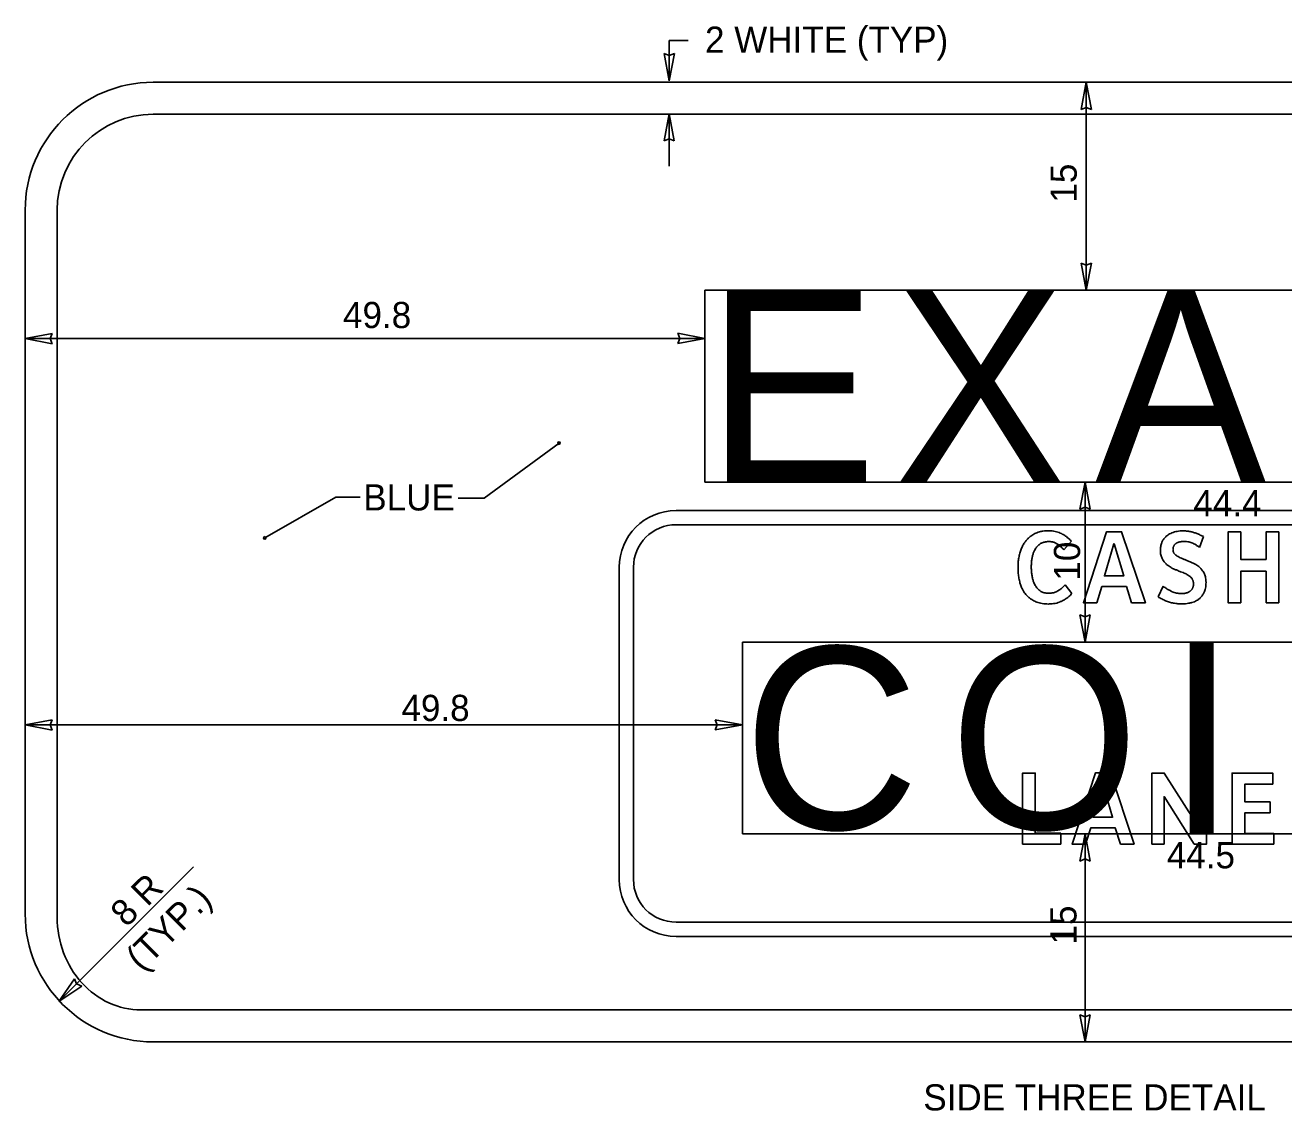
# Model space of a CAD drawing. Extents: x 319706 to 320346, y 1621790 to 1622121.
# Drawn here: x 319720.4 to 319787.7, y 1622061.2 to 1622119.2 of the extents above; entities that cross this region are included whole.
import ezdxf

# ---------------------------------------------------------------- set-up
doc = ezdxf.new("R2010")
doc.units = 0
for name, color, linetype in [('1', 7, 'Continuous'), ('52', 7, 'Continuous'), ('GSOutline', 7, 'Continuous'), ('SignPanel', 7, 'Continuous'), ('SOILS_SP83_SHP', 7, 'Continuous')]:
    doc.layers.add(name, color=color, linetype=linetype)

msp = doc.modelspace()

# ---------------------------------------------------------------- linework, layer by layer
at = {"layer": '1'}
for p, q in [((319754.849, 1622116.226), (319754.849, 1622118.372)), ((319754.849, 1622118.372), (319755.859, 1622118.372)), ((319777.142, 1622116.142), (319777.142, 1622105.027)), ((319754.849, 1622111.65), (319754.849, 1622114.46)), ((319720.417, 1622102.447), (319756.748, 1622102.447)), ((319744.954, 1622093.91), (319748.959, 1622096.856)), ((319777.075, 1622094.767), (319777.075, 1622086.218)), ((319737.031, 1622093.965), (319733.225, 1622091.783)), ((319738.317, 1622093.965), (319737.031, 1622093.965)), ((319743.57, 1622093.91), (319744.954, 1622093.91)), ((319720.417, 1622081.786), (319758.755, 1622081.786)), ((319722.216, 1622066.995), (319729.415, 1622074.193))]:
    msp.add_line(p, q, dxfattribs=at)
for centre in [(319748.958, 1622096.855), (319733.224, 1622091.782)]:
    msp.add_ellipse(centre, major_axis=(0, 0.0707), ratio=0.906668, dxfattribs=at)
at = {"layer": '52'}
for p, q in [((319754.849, 1622117.566), (319754.579, 1622117.676)), ((319754.579, 1622117.676), (319754.849, 1622116.226)), ((319754.849, 1622116.226), (319755.129, 1622117.676)), ((319755.129, 1622117.676), (319754.849, 1622117.566)), ((319777.142, 1622116.142), (319776.862, 1622114.692)), ((319777.412, 1622114.692), (319777.142, 1622116.142)), ((319776.862, 1622114.692), (319777.142, 1622114.802)), ((319777.142, 1622114.802), (319777.412, 1622114.692)), ((319754.849, 1622114.46), (319754.569, 1622113.01)), ((319755.119, 1622113.01), (319754.849, 1622114.46)), ((319754.569, 1622113.01), (319754.849, 1622113.12)), ((319754.849, 1622113.12), (319755.119, 1622113.01)), ((319777.142, 1622106.367), (319776.872, 1622106.477)), ((319776.872, 1622106.477), (319777.142, 1622105.027)), ((319777.142, 1622105.027), (319777.422, 1622106.477)), ((319777.422, 1622106.477), (319777.142, 1622106.367)), ((319721.867, 1622102.717), (319720.417, 1622102.447)), ((319721.757, 1622102.447), (319721.867, 1622102.717)), ((319756.748, 1622102.447), (319755.298, 1622102.727)), ((319755.298, 1622102.727), (319755.408, 1622102.447)), ((319720.417, 1622102.447), (319721.867, 1622102.167)), ((319721.867, 1622102.167), (319721.757, 1622102.447)), ((319755.408, 1622102.447), (319755.298, 1622102.177)), ((319755.298, 1622102.177), (319756.748, 1622102.447)), ((319777.075, 1622094.767), (319776.795, 1622093.317)), ((319777.345, 1622093.317), (319777.075, 1622094.767)), ((319776.795, 1622093.317), (319777.075, 1622093.427)), ((319777.075, 1622093.427), (319777.345, 1622093.317)), ((319777.075, 1622087.558), (319776.805, 1622087.668)), ((319776.805, 1622087.668), (319777.075, 1622086.218)), ((319777.075, 1622086.218), (319777.355, 1622087.668)), ((319777.355, 1622087.668), (319777.075, 1622087.558)), ((319721.867, 1622082.056), (319720.417, 1622081.786)), ((319720.417, 1622081.786), (319721.867, 1622081.506)), ((319721.757, 1622081.786), (319721.867, 1622082.056)), ((319721.867, 1622081.506), (319721.757, 1622081.786)), ((319758.755, 1622081.786), (319757.305, 1622082.066)), ((319757.305, 1622082.066), (319757.415, 1622081.786)), ((319757.415, 1622081.786), (319757.305, 1622081.516)), ((319757.305, 1622081.516), (319758.755, 1622081.786)), ((319777.075, 1622075.958), (319776.795, 1622074.508)), ((319777.345, 1622074.508), (319777.075, 1622075.958)), ((319776.795, 1622074.508), (319777.075, 1622074.618)), ((319777.075, 1622074.618), (319777.345, 1622074.508)), ((319723.05, 1622068.212), (319722.216, 1622066.995)), ((319723.163, 1622067.943), (319723.05, 1622068.212)), ((319722.216, 1622066.995), (319723.439, 1622067.823)), ((319723.439, 1622067.823), (319723.163, 1622067.943)), ((319777.075, 1622066.182), (319776.805, 1622066.292)), ((319776.805, 1622066.292), (319777.075, 1622064.842)), ((319777.075, 1622064.842), (319777.355, 1622066.292)), ((319777.355, 1622066.292), (319777.075, 1622066.182))]:
    msp.add_line(p, q, dxfattribs=at)
at = {"layer": 'GSOutline'}
for p, q in [((319803.779, 1622093.246), (319755.212, 1622093.246)), ((319803.779, 1622092.488), (319755.212, 1622092.488)), ((319752.176, 1622090.211), (319752.176, 1622073.516)), ((319752.935, 1622090.211), (319752.935, 1622073.516)), ((319755.212, 1622071.24), (319803.779, 1622071.24)), ((319755.212, 1622070.481), (319803.779, 1622070.481))]:
    msp.add_line(p, q, dxfattribs=at)
for points in [[(319779.566, 1622088.314), (319779.289, 1622089.181), (319777.977, 1622089.181), (319777.7, 1622088.314), (319776.988, 1622088.314), (319778.231, 1622092.117), (319779.031, 1622092.117), (319780.302, 1622088.314), (319779.566, 1622088.314)], [(319783.404, 1622091.852), (319783.203, 1622091.279)], [(319786.753, 1622088.314), (319786.753, 1622090.001), (319785.402, 1622090.001), (319785.402, 1622088.314), (319784.72, 1622088.314), (319784.72, 1622092.108), (319785.402, 1622092.108), (319785.402, 1622090.637), (319786.753, 1622090.637), (319786.753, 1622092.108), (319787.435, 1622092.108), (319787.435, 1622088.314), (319786.753, 1622088.314)], [(319776.351, 1622091.61), (319775.945, 1622091.14)], [(319778.641, 1622091.472), (319778.622, 1622091.473), (319778.114, 1622089.752), (319779.149, 1622089.752), (319778.641, 1622091.472)], [(319776.014, 1622089.277), (319776.378, 1622088.803)], [(319780.987, 1622088.63), (319781.245, 1622089.199)], [(319773.734, 1622075.413), (319773.734, 1622079.208), (319774.416, 1622079.208), (319774.416, 1622075.994), (319775.777, 1622075.994), (319775.777, 1622075.413), (319773.734, 1622075.413)], [(319778.965, 1622075.413), (319778.689, 1622076.28), (319777.377, 1622076.28), (319777.1, 1622075.413), (319776.387, 1622075.413), (319777.631, 1622079.217), (319778.431, 1622079.217), (319779.701, 1622075.413), (319778.965, 1622075.413)], [(319782.915, 1622075.413), (319781.31, 1622077.955), (319781.301, 1622077.955), (319781.301, 1622075.413), (319780.651, 1622075.413), (319780.651, 1622079.208), (319781.31, 1622079.208), (319782.906, 1622076.692), (319782.914, 1622076.692), (319782.915, 1622079.208), (319783.569, 1622079.208), (319783.569, 1622075.413), (319782.915, 1622075.413)], [(319784.939, 1622075.413), (319784.939, 1622079.208), (319787.11, 1622079.208), (319787.11, 1622078.627), (319785.621, 1622078.627), (319785.621, 1622077.672), (319786.967, 1622077.672), (319786.967, 1622077.087), (319785.621, 1622077.087), (319785.621, 1622075.98), (319787.168, 1622075.98), (319787.168, 1622075.413), (319784.939, 1622075.413)], [(319778.04, 1622078.571), (319778.021, 1622078.572), (319777.513, 1622076.852), (319778.548, 1622076.852), (319778.04, 1622078.571)]]:
    msp.add_lwpolyline(points, dxfattribs=at)
for centre, radius, start, end in [((319755.212, 1622090.211), 3.035, 90, 180), ((319755.212, 1622090.211), 2.277, 90, 180), ((319755.212, 1622073.516), 3.035, 180, 270), ((319755.212, 1622073.516), 2.277, 180, 270)]:
    msp.add_arc(centre, radius, start, end, dxfattribs=at)
for points in [[(319773.492, 1622090.218), (319773.493, 1622090.283), (319773.497, 1622090.474), (319773.53, 1622090.724), (319773.586, 1622090.965), (319773.657, 1622091.19), (319773.756, 1622091.399), (319773.867, 1622091.564), (319773.952, 1622091.673), (319774.047, 1622091.773), (319774.174, 1622091.88), (319774.291, 1622091.957), (319774.391, 1622092.012), (319774.496, 1622092.061), (319774.639, 1622092.111), (319774.824, 1622092.15), (319774.987, 1622092.166), (319775.087, 1622092.168), (319775.122, 1622092.168)], [(319775.122, 1622092.168), (319775.153, 1622092.168), (319775.242, 1622092.166), (319775.387, 1622092.152), (319775.554, 1622092.118), (319775.685, 1622092.074), (319775.81, 1622092.019), (319775.984, 1622091.923), (319776.175, 1622091.781), (319776.305, 1622091.655), (319776.351, 1622091.61)], [(319781.104, 1622091.13), (319781.105, 1622091.153), (319781.105, 1622091.218), (319781.116, 1622091.322), (319781.141, 1622091.439), (319781.172, 1622091.53), (319781.204, 1622091.597), (319781.239, 1622091.66), (319781.288, 1622091.734), (319781.356, 1622091.814), (319781.419, 1622091.873), (319781.488, 1622091.927), (319781.591, 1622091.996), (319781.721, 1622092.058), (319781.86, 1622092.102), (319782.005, 1622092.136), (319782.155, 1622092.156), (319782.269, 1622092.158), (319782.307, 1622092.159)], [(319782.307, 1622092.159), (319782.358, 1622092.158), (319782.505, 1622092.155), (319782.698, 1622092.127), (319782.882, 1622092.079), (319783.061, 1622092.018), (319783.236, 1622091.943), (319783.361, 1622091.875), (319783.404, 1622091.852)], [(319775.138, 1622091.587), (319775.119, 1622091.587), (319775.063, 1622091.586), (319774.972, 1622091.576), (319774.869, 1622091.553), (319774.789, 1622091.524), (319774.729, 1622091.495), (319774.672, 1622091.462), (319774.604, 1622091.414), (319774.531, 1622091.346), (319774.476, 1622091.282), (319774.436, 1622091.225), (319774.367, 1622091.114), (319774.306, 1622090.969), (319774.259, 1622090.792), (319774.224, 1622090.612), (319774.205, 1622090.419), (319774.203, 1622090.27), (319774.202, 1622090.218)], [(319775.945, 1622091.14), (319775.914, 1622091.175), (319775.855, 1622091.241), (319775.777, 1622091.318), (319775.7, 1622091.386), (319775.637, 1622091.433), (319775.572, 1622091.474), (319775.507, 1622091.509), (319775.439, 1622091.538), (319775.369, 1622091.559), (319775.295, 1622091.576), (319775.218, 1622091.586), (319775.158, 1622091.587), (319775.138, 1622091.587)], [(319782.183, 1622089.977), (319782.12, 1622090.002), (319781.993, 1622090.052), (319781.836, 1622090.119), (319781.681, 1622090.193), (319781.564, 1622090.265), (319781.47, 1622090.337), (319781.406, 1622090.392), (319781.335, 1622090.465), (319781.263, 1622090.56), (319781.21, 1622090.65), (319781.171, 1622090.731), (319781.14, 1622090.821), (319781.116, 1622090.938), (319781.105, 1622091.042), (319781.105, 1622091.108), (319781.104, 1622091.13)], [(319782.357, 1622091.592), (319782.319, 1622091.591), (319782.263, 1622091.59), (319782.189, 1622091.58), (319782.136, 1622091.572), (319782.07, 1622091.556), (319782.015, 1622091.534), (319781.972, 1622091.511), (319781.952, 1622091.499), (319781.926, 1622091.481), (319781.896, 1622091.456), (319781.864, 1622091.422), (319781.841, 1622091.391), (319781.825, 1622091.364), (319781.809, 1622091.335), (319781.795, 1622091.295), (319781.783, 1622091.243), (319781.778, 1622091.197), (319781.778, 1622091.168), (319781.777, 1622091.158)], [(319781.777, 1622091.158), (319781.778, 1622091.149), (319781.778, 1622091.122), (319781.784, 1622091.078), (319781.8, 1622091.027), (319781.819, 1622090.989), (319781.838, 1622090.96), (319781.876, 1622090.911), (319781.931, 1622090.859), (319782.001, 1622090.81), (319782.094, 1622090.753), (319782.218, 1622090.696), (319782.373, 1622090.636), (319782.466, 1622090.599), (319782.513, 1622090.581)], [(319783.203, 1622091.279), (319783.17, 1622091.302), (319783.075, 1622091.369), (319782.943, 1622091.446), (319782.824, 1622091.501), (319782.739, 1622091.535), (319782.631, 1622091.567), (319782.496, 1622091.588), (319782.398, 1622091.591), (319782.357, 1622091.592)], [(319782.513, 1622090.581), (319782.574, 1622090.557), (319782.697, 1622090.508), (319782.849, 1622090.439), (319782.997, 1622090.362), (319783.109, 1622090.287), (319783.198, 1622090.213), (319783.258, 1622090.156), (319783.326, 1622090.081), (319783.394, 1622089.983), (319783.444, 1622089.891), (319783.481, 1622089.808), (319783.51, 1622089.716), (319783.538, 1622089.576), (319783.541, 1622089.47), (319783.543, 1622089.404)], [(319775.119, 1622088.249), (319775.05, 1622088.251), (319774.948, 1622088.253), (319774.785, 1622088.273), (319774.633, 1622088.303), (319774.49, 1622088.349), (319774.383, 1622088.396), (319774.284, 1622088.448), (319774.167, 1622088.521), (319774.039, 1622088.625), (319773.945, 1622088.723), (319773.876, 1622088.809), (319773.812, 1622088.899), (319773.724, 1622089.045), (319773.643, 1622089.233), (319773.582, 1622089.434), (319773.528, 1622089.684), (319773.497, 1622089.947), (319773.493, 1622090.149), (319773.492, 1622090.218)], [(319774.202, 1622090.218), (319774.204, 1622090.132), (319774.209, 1622089.961), (319774.238, 1622089.75), (319774.28, 1622089.55), (319774.332, 1622089.4), (319774.391, 1622089.278), (319774.438, 1622089.198), (319774.49, 1622089.124), (319774.563, 1622089.044), (319774.631, 1622088.986), (319774.689, 1622088.944), (319774.751, 1622088.907), (319774.838, 1622088.869), (319774.951, 1622088.839), (319775.053, 1622088.827), (319775.117, 1622088.826), (319775.139, 1622088.826)], [(319782.87, 1622089.335), (319782.87, 1622089.346), (319782.869, 1622089.378), (319782.864, 1622089.429), (319782.85, 1622089.487), (319782.833, 1622089.533), (319782.815, 1622089.567), (319782.796, 1622089.599), (319782.763, 1622089.646), (319782.717, 1622089.696), (319782.665, 1622089.74), (319782.598, 1622089.789), (319782.525, 1622089.833), (319782.425, 1622089.881), (319782.317, 1622089.927), (319782.228, 1622089.96), (319782.183, 1622089.977)], [(319775.139, 1622088.826), (319775.16, 1622088.826), (319775.222, 1622088.827), (319775.323, 1622088.839), (319775.439, 1622088.867), (319775.531, 1622088.902), (319775.618, 1622088.946), (319775.744, 1622089.026), (319775.883, 1622089.141), (319775.98, 1622089.241), (319776.014, 1622089.277)], [(319781.245, 1622089.199), (319781.282, 1622089.173), (319781.392, 1622089.093), (319781.548, 1622089.001), (319781.689, 1622088.93), (319781.792, 1622088.885), (319781.898, 1622088.849), (319782.031, 1622088.821), (319782.144, 1622088.809), (319782.213, 1622088.808), (319782.236, 1622088.807)], [(319782.236, 1622088.807), (319782.256, 1622088.808), (319782.316, 1622088.808), (319782.394, 1622088.818), (319782.471, 1622088.833), (319782.544, 1622088.853), (319782.613, 1622088.882), (319782.667, 1622088.916), (319782.704, 1622088.942), (319782.737, 1622088.972), (319782.773, 1622089.012), (319782.799, 1622089.05), (319782.817, 1622089.082), (319782.834, 1622089.118), (319782.851, 1622089.166), (319782.867, 1622089.242), (319782.869, 1622089.299), (319782.87, 1622089.335)], [(319783.543, 1622089.404), (319783.542, 1622089.356), (319783.539, 1622089.24), (319783.515, 1622089.083), (319783.478, 1622088.96), (319783.447, 1622088.885), (319783.414, 1622088.815), (319783.366, 1622088.733), (319783.299, 1622088.643), (319783.235, 1622088.576), (319783.179, 1622088.527), (319783.121, 1622088.482), (319783.043, 1622088.431), (319782.923, 1622088.371), (319782.793, 1622088.325), (319782.613, 1622088.283), (319782.443, 1622088.262), (319782.314, 1622088.259), (319782.269, 1622088.259)], [(319776.378, 1622088.803), (319776.334, 1622088.76), (319776.206, 1622088.636), (319776.013, 1622088.499), (319775.834, 1622088.404), (319775.703, 1622088.347), (319775.565, 1622088.302), (319775.392, 1622088.266), (319775.242, 1622088.251), (319775.15, 1622088.25), (319775.119, 1622088.249)], [(319782.269, 1622088.259), (319782.208, 1622088.26), (319782.034, 1622088.263), (319781.805, 1622088.293), (319781.59, 1622088.347), (319781.383, 1622088.418), (319781.18, 1622088.512), (319781.036, 1622088.6), (319780.987, 1622088.63)]]:
    msp.add_open_spline(points, degree=3, dxfattribs=at)
at = {"layer": 'SignPanel'}
for p, q in [((319727.257, 1622116.142), (319836.697, 1622116.142)), ((319727.257, 1622114.432), (319836.697, 1622114.432)), ((319720.417, 1622071.682), (319720.417, 1622109.302)), ((319722.127, 1622071.503), (319722.127, 1622109.302)), ((319777.075, 1622064.842), (319777.075, 1622075.958)), ((319726.616, 1622066.552), (319836.697, 1622066.552)), ((319727.257, 1622064.842), (319836.697, 1622064.842))]:
    msp.add_line(p, q, dxfattribs=at)
for centre, radius, start, end in [((319727.257, 1622109.301), 6.84, 90, 180), ((319727.257, 1622109.301), 5.13, 90, 180), ((319727.257, 1622071.681), 6.84, 180, 270)]:
    msp.add_arc(centre, radius, start, end, dxfattribs=at)
msp.add_ellipse((319726.615, 1622071.502), major_axis=(0, 4.951), ratio=0.906668, start_param=1.570796, end_param=3.141593, dxfattribs=at)
at = {"layer": 'SOILS_SP83_SHP'}
for p, q in [((319756.748, 1622105.027), (319807.16, 1622105.027)), ((319756.748, 1622094.767), (319756.748, 1622105.027)), ((319756.748, 1622094.767), (319807.16, 1622094.767)), ((319758.755, 1622086.218), (319804.916, 1622086.218)), ((319758.755, 1622075.958), (319758.755, 1622086.218)), ((319758.755, 1622075.958), (319804.916, 1622075.958))]:
    msp.add_line(p, q, dxfattribs=at)

# ---------------------------------------------------------------- texts
at = {"layer": '1'}
for s, p in [('2 WHITE (TYP)', (319756.761, 1622117.721)), ('49.8', (319737.408, 1622103.001)), ('BLUE', (319738.493, 1622093.25)), ('44.4', (319782.866, 1622092.936)), ('49.8', (319740.532, 1622081.995)), ('44.5', (319781.448, 1622074.118)), ('SIDE THREE DETAIL', (319768.431, 1622061.174))]:
    msp.add_text(s, height=1.4, dxfattribs=at).set_placement(p)
for s, rotation, p in [('15', 90, (319776.629, 1622109.71)), ('10', 90, (319776.812, 1622089.499)), ('8 R', 45, (319725.837, 1622070.922)), ('(TYP.)', 45, (319726.657, 1622068.552)), ('15', 90, (319776.619, 1622070.046))]:
    msp.add_text(s, height=1.4, rotation=rotation, dxfattribs=at).set_placement(p)
at = {"layer": 'SignPanel'}
for s, height, p in [('E', 10.26, (319756.801, 1622094.794)), ('X', 10.26, (319766.886, 1622094.79)), ('A', 10.26, (319777.607, 1622094.761)), ('C', 9.747, (319758.802, 1622076.213)), ('O', 9.747, (319769.833, 1622076.213)), ('I', 10.26, (319781.399, 1622075.97))]:
    msp.add_text(s, height=height, dxfattribs=at).set_placement(p)

doc.saveas('drawing.dxf')
